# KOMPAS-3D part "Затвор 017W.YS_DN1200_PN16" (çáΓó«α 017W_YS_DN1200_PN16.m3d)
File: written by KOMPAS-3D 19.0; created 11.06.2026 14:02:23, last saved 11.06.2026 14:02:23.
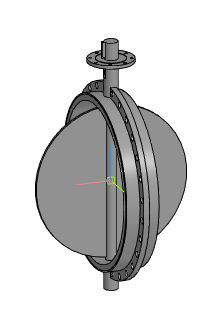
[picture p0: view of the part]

Document properties: Автор: Евгений; Полное имя файла: Z:\3.Личные\kachalov\001_3d для проектировщиков\x.x Тип 017W.Y(S) Затвор дисковый поворотный межфланцевый\_stp_Затвор 017W.YS_DN32-DN1200\Затвор 017W_YS_DN1200_PN16.m3d

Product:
- Part/product: Затвор 017W.YS_DN1200_PN16

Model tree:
1. Операция без истории:1  (labels: Затвор 017W.YS_DN1200_PN16)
